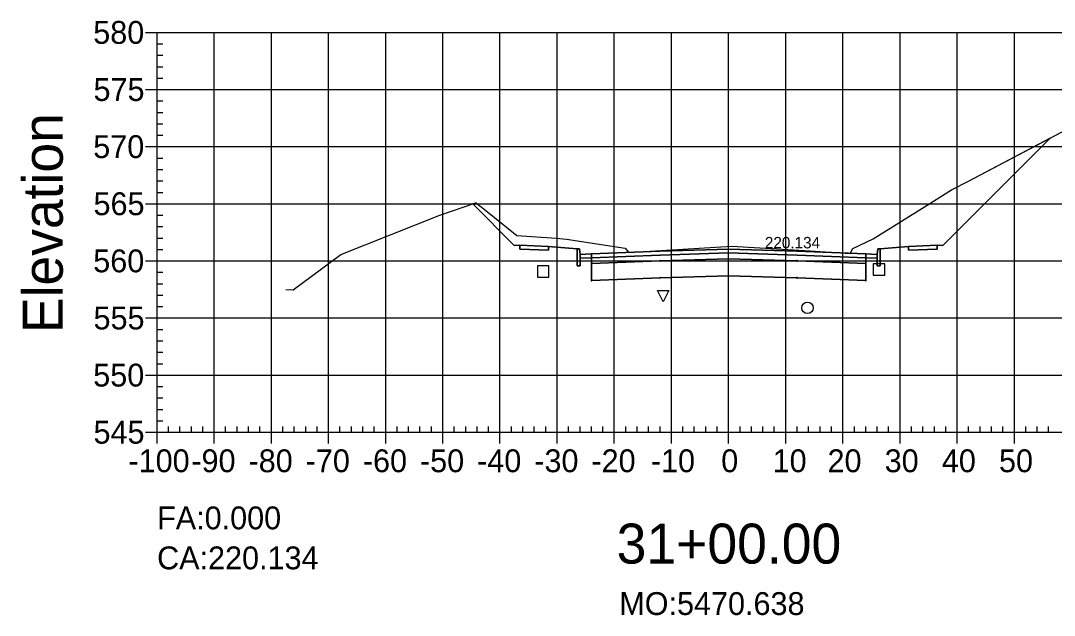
# Model space of a CAD drawing. Extents: x 704834 to 709892, y 372981 to 377533.
# Drawn here: x 706563 to 706743.9, y 373790.8 to 373894.9 of the extents above; entities that cross this region are included whole.
import ezdxf

# ---------------------------------------------------------------- set-up
doc = ezdxf.new("R2010")
doc.units = 0
for name, color, linetype in [('1', 7, 'Continuous'), ('10', 7, 'Continuous'), ('13', 7, 'Continuous'), ('14', 7, 'Continuous'), ('4', 7, 'Continuous'), ('57', 7, 'Continuous'), ('59', 7, 'Continuous'), ('60', 7, 'Continuous'), ('Default_Xsect', 7, 'Continuous'), ('Existing', 7, 'Continuous')]:
    doc.layers.add(name, color=color, linetype=linetype)

msp = doc.modelspace()

# ---------------------------------------------------------------- linework, layer by layer
for points in [[(706724.37, 373855.51), (706743.22, 373874.36)], [(706649.37, 373855.51), (706642.11, 373862.78)], [(706650.37, 373855.55), (706649.37, 373855.51)], [(706660.37, 373854.95), (706655.37, 373855.35)], [(706713.37, 373854.95), (706718.37, 373855.35)], [(706723.37, 373855.55), (706724.37, 373855.51)]]:
    msp.add_lwpolyline(points)
for points in [[(706655.37, 373855.35), (706650.37, 373855.55), (706650.37, 373854.88), (706655.37, 373854.68)], [(706718.37, 373854.68), (706723.37, 373854.88), (706723.37, 373855.55), (706718.37, 373855.35)], [(706660.87, 373853.95), (706660.79, 373854.95), (706660.37, 373854.95), (706660.37, 373851.95), (706660.87, 373851.95)], [(706662.87, 373854.03), (706660.87, 373853.95), (706660.87, 373853.28), (706662.87, 373853.36)], [(706686.87, 373854.2), (706698.87, 373853.84), (706710.87, 373853.36), (706710.87, 373854.03), (706698.87, 373854.51), (706686.87, 373854.87), (706674.87, 373854.51), (706662.87, 373854.03), (706662.87, 373853.36), (706674.87, 373853.84)], [(706686.87, 373853.2), (706698.87, 373852.84), (706710.87, 373852.36), (706710.87, 373853.36), (706698.87, 373853.84), (706686.87, 373854.2), (706674.87, 373853.84), (706662.87, 373853.36), (706662.87, 373852.36), (706674.87, 373852.84)], [(706686.82, 373854.15), (706686.92, 373854.15), (706686.92, 373854.25), (706686.82, 373854.25)], [(706710.87, 373853.36), (706712.87, 373853.28), (706712.87, 373853.95), (706710.87, 373854.03)], [(706712.87, 373851.95), (706713.37, 373851.95), (706713.37, 373854.95), (706712.96, 373854.95), (706712.87, 373853.95)], [(706662.82, 373852.31), (706662.92, 373852.31), (706662.92, 373852.41), (706662.82, 373852.41)], [(706686.87, 373850.2), (706698.87, 373849.84), (706710.87, 373849.36), (706710.87, 373852.36), (706698.87, 373852.84), (706686.87, 373853.2), (706674.87, 373852.84), (706662.87, 373852.36), (706662.87, 373849.36), (706674.87, 373849.84)], [(706674.82, 373852.79), (706674.92, 373852.79), (706674.92, 373852.89), (706674.82, 373852.89)], [(706686.82, 373853.15), (706686.92, 373853.15), (706686.92, 373853.25), (706686.82, 373853.25)], [(706698.82, 373852.79), (706698.92, 373852.79), (706698.92, 373852.89), (706698.82, 373852.89)], [(706710.82, 373852.31), (706710.92, 373852.31), (706710.92, 373852.41), (706710.82, 373852.41)], [(706674.82, 373849.79), (706674.92, 373849.79), (706674.92, 373849.89), (706674.82, 373849.89)], [(706686.82, 373850.15), (706686.92, 373850.15), (706686.92, 373850.25), (706686.82, 373850.25)], [(706698.82, 373849.79), (706698.92, 373849.79), (706698.92, 373849.89), (706698.82, 373849.89)], [(706662.82, 373849.31), (706662.92, 373849.31), (706662.92, 373849.41), (706662.82, 373849.41)], [(706710.82, 373849.31), (706710.92, 373849.31), (706710.92, 373849.41), (706710.82, 373849.41)]]:
    msp.add_lwpolyline(points, close=True)
at = {"layer": '1'}
for points in [[(706642.11, 373862.78), (706642.47, 373862.9), (706642.55, 373862.9), (706642.56, 373863.03), (706644.1, 373861.87), (706649.84, 373857.24), (706656.74, 373856.82), (706658.53, 373856.6), (706668.78, 373855.06), (706669.3, 373854.42), (706669.38, 373854.27), (706673.17, 373854.51), (706687.42, 373855.4), (706701.15, 373854.56), (706708.14, 373854.12), (706708.21, 373854.24), (706708.6, 373854.97), (706712.15, 373856.68), (706721.63, 373862.55), (706725.9, 373865.23), (706728.86, 373866.79), (706743.22, 373874.36), (706724.37, 373855.51), (706723.37, 373855.55), (706723.37, 373854.88), (706718.37, 373854.68), (706718.37, 373855.35), (706713.37, 373854.95), (706713.37, 373851.95), (706712.87, 373851.95), (706712.87, 373853.28), (706710.87, 373853.36), (706710.87, 373852.36), (706710.87, 373849.36), (706698.87, 373849.84), (706686.87, 373850.2), (706674.87, 373849.84), (706662.87, 373849.36), (706662.87, 373852.36), (706662.87, 373853.36), (706660.87, 373853.28), (706660.87, 373851.95), (706660.37, 373851.95), (706660.37, 373854.95), (706655.37, 373855.35), (706655.37, 373854.68), (706650.37, 373854.88), (706650.37, 373855.55), (706649.37, 373855.51)], [(706675.44, 373845.65), (706674.44, 373847.65), (706676.44, 373847.65)]]:
    msp.add_lwpolyline(points, close=True, dxfattribs=at)
at = {"layer": '10'}
msp.add_lwpolyline([(706653.43, 373849.96), (706655.43, 373849.96), (706655.43, 373851.96), (706653.43, 373851.96)], close=True, dxfattribs=at)
at = {"layer": '13'}
msp.add_circle((706700.67, 373844.59), 1, dxfattribs=at)
at = {"layer": '14'}
for points in [[(706743.22, 373874.36), (706743.22, 373874.41), (706743.22, 373874.36), (706743.17, 373874.36), (706743.22, 373874.36), (706743.22, 373874.31), (706743.22, 373874.36), (706743.27, 373874.36)], [(706642.11, 373862.78), (706642.11, 373862.83), (706642.11, 373862.78), (706642.06, 373862.78), (706642.11, 373862.78), (706642.11, 373862.73), (706642.11, 373862.78), (706642.16, 373862.78)], [(706662.87, 373854.03), (706662.87, 373854.08), (706662.87, 373854.03), (706662.82, 373854.03), (706662.87, 373854.03), (706662.87, 373853.98), (706662.87, 373854.03), (706662.92, 373854.03)], [(706674.87, 373854.51), (706674.87, 373854.56), (706674.87, 373854.51), (706674.82, 373854.51), (706674.87, 373854.51), (706674.87, 373854.46), (706674.87, 373854.51), (706674.92, 373854.51)], [(706686.87, 373854.87), (706686.87, 373854.92), (706686.87, 373854.87), (706686.82, 373854.87), (706686.87, 373854.87), (706686.87, 373854.82), (706686.87, 373854.87), (706686.92, 373854.87)], [(706698.87, 373854.51), (706698.87, 373854.56), (706698.87, 373854.51), (706698.82, 373854.51), (706698.87, 373854.51), (706698.87, 373854.46), (706698.87, 373854.51), (706698.92, 373854.51)], [(706710.87, 373854.03), (706710.87, 373854.08), (706710.87, 373854.03), (706710.82, 373854.03), (706710.87, 373854.03), (706710.87, 373853.98), (706710.87, 373854.03), (706710.92, 373854.03)]]:
    msp.add_lwpolyline(points, dxfattribs=at)
at = {"layer": '4'}
msp.add_lwpolyline([(706712.18, 373850.32), (706714.18, 373850.32), (706714.18, 373852.32), (706712.18, 373852.32)], close=True, dxfattribs=at)
at = {"layer": '57'}
for p, q in [((706584.87, 373892.82), (706586.87, 373892.82)), ((706586.87, 373892.82), (706786.87, 373892.82)), ((706586.87, 373822.82), (706586.87, 373892.82)), ((706586.87, 373822.82), (706586.87, 373892.82)), ((706596.87, 373822.82), (706596.87, 373892.82)), ((706606.87, 373822.82), (706606.87, 373892.82)), ((706616.87, 373822.82), (706616.87, 373892.82)), ((706626.87, 373822.82), (706626.87, 373892.82)), ((706636.87, 373822.82), (706636.87, 373892.82)), ((706646.87, 373822.82), (706646.87, 373892.82)), ((706656.87, 373822.82), (706656.87, 373892.82)), ((706666.87, 373822.82), (706666.87, 373892.82)), ((706676.87, 373822.82), (706676.87, 373892.82)), ((706686.87, 373822.82), (706686.87, 373892.82)), ((706696.87, 373822.82), (706696.87, 373892.82)), ((706706.87, 373822.82), (706706.87, 373892.82)), ((706716.87, 373822.82), (706716.87, 373892.82)), ((706726.87, 373822.82), (706726.87, 373892.82)), ((706736.87, 373822.82), (706736.87, 373892.82)), ((706586.87, 373890.82), (706587.87, 373890.82)), ((706586.87, 373888.82), (706587.87, 373888.82)), ((706586.87, 373886.82), (706587.87, 373886.82)), ((706586.87, 373884.82), (706587.87, 373884.82)), ((706584.87, 373882.82), (706586.87, 373882.82)), ((706586.87, 373882.82), (706786.87, 373882.82)), ((706586.87, 373880.82), (706587.87, 373880.82)), ((706586.87, 373878.82), (706587.87, 373878.82)), ((706586.87, 373876.82), (706587.87, 373876.82)), ((706586.87, 373874.82), (706587.87, 373874.82)), ((706584.87, 373872.82), (706586.87, 373872.82)), ((706586.87, 373872.82), (706786.87, 373872.82)), ((706586.87, 373870.82), (706587.87, 373870.82)), ((706586.87, 373868.82), (706587.87, 373868.82)), ((706586.87, 373866.82), (706587.87, 373866.82)), ((706586.87, 373864.82), (706587.87, 373864.82)), ((706584.87, 373862.82), (706586.87, 373862.82)), ((706586.87, 373862.82), (706786.87, 373862.82)), ((706586.87, 373860.82), (706587.87, 373860.82)), ((706586.87, 373858.82), (706587.87, 373858.82)), ((706586.87, 373856.82), (706587.87, 373856.82)), ((706586.87, 373854.82), (706587.87, 373854.82)), ((706584.87, 373852.82), (706586.87, 373852.82)), ((706586.87, 373852.82), (706786.87, 373852.82)), ((706586.87, 373850.82), (706587.87, 373850.82)), ((706586.87, 373848.82), (706587.87, 373848.82)), ((706586.87, 373846.82), (706587.87, 373846.82)), ((706586.87, 373844.82), (706587.87, 373844.82)), ((706584.87, 373842.82), (706586.87, 373842.82)), ((706586.87, 373842.82), (706786.87, 373842.82)), ((706586.87, 373840.82), (706587.87, 373840.82)), ((706586.87, 373838.82), (706587.87, 373838.82)), ((706586.87, 373836.82), (706587.87, 373836.82)), ((706586.87, 373834.82), (706587.87, 373834.82)), ((706584.87, 373832.82), (706586.87, 373832.82)), ((706586.87, 373832.82), (706786.87, 373832.82)), ((706586.87, 373830.82), (706587.87, 373830.82)), ((706586.87, 373828.82), (706587.87, 373828.82)), ((706586.87, 373826.82), (706587.87, 373826.82)), ((706586.87, 373824.82), (706587.87, 373824.82)), ((706584.87, 373822.82), (706586.87, 373822.82)), ((706586.87, 373822.82), (706786.87, 373822.82)), ((706586.87, 373822.82), (706786.87, 373822.82)), ((706586.87, 373820.82), (706586.87, 373822.82)), ((706588.87, 373822.82), (706588.87, 373823.82)), ((706590.87, 373822.82), (706590.87, 373823.82)), ((706592.87, 373822.82), (706592.87, 373823.82)), ((706594.87, 373822.82), (706594.87, 373823.82)), ((706596.87, 373820.82), (706596.87, 373822.82)), ((706598.87, 373822.82), (706598.87, 373823.82)), ((706600.87, 373822.82), (706600.87, 373823.82)), ((706602.87, 373822.82), (706602.87, 373823.82)), ((706604.87, 373822.82), (706604.87, 373823.82)), ((706606.87, 373820.82), (706606.87, 373822.82)), ((706608.87, 373822.82), (706608.87, 373823.82)), ((706610.87, 373822.82), (706610.87, 373823.82)), ((706612.87, 373822.82), (706612.87, 373823.82)), ((706614.87, 373822.82), (706614.87, 373823.82)), ((706616.87, 373820.82), (706616.87, 373822.82)), ((706618.87, 373822.82), (706618.87, 373823.82)), ((706620.87, 373822.82), (706620.87, 373823.82)), ((706622.87, 373822.82), (706622.87, 373823.82)), ((706624.87, 373822.82), (706624.87, 373823.82)), ((706626.87, 373820.82), (706626.87, 373822.82)), ((706628.87, 373822.82), (706628.87, 373823.82)), ((706630.87, 373822.82), (706630.87, 373823.82)), ((706632.87, 373822.82), (706632.87, 373823.82)), ((706634.87, 373822.82), (706634.87, 373823.82)), ((706636.87, 373820.82), (706636.87, 373822.82)), ((706638.87, 373822.82), (706638.87, 373823.82)), ((706640.87, 373822.82), (706640.87, 373823.82)), ((706642.87, 373822.82), (706642.87, 373823.82)), ((706644.87, 373822.82), (706644.87, 373823.82)), ((706646.87, 373820.82), (706646.87, 373822.82)), ((706648.87, 373822.82), (706648.87, 373823.82)), ((706650.87, 373822.82), (706650.87, 373823.82)), ((706652.87, 373822.82), (706652.87, 373823.82)), ((706654.87, 373822.82), (706654.87, 373823.82)), ((706656.87, 373820.82), (706656.87, 373822.82)), ((706658.87, 373822.82), (706658.87, 373823.82)), ((706660.87, 373822.82), (706660.87, 373823.82)), ((706662.87, 373822.82), (706662.87, 373823.82)), ((706664.87, 373822.82), (706664.87, 373823.82)), ((706666.87, 373820.82), (706666.87, 373822.82)), ((706668.87, 373822.82), (706668.87, 373823.82)), ((706670.87, 373822.82), (706670.87, 373823.82)), ((706672.87, 373822.82), (706672.87, 373823.82)), ((706674.87, 373822.82), (706674.87, 373823.82)), ((706676.87, 373820.82), (706676.87, 373822.82)), ((706678.87, 373822.82), (706678.87, 373823.82)), ((706680.87, 373822.82), (706680.87, 373823.82)), ((706682.87, 373822.82), (706682.87, 373823.82)), ((706684.87, 373822.82), (706684.87, 373823.82)), ((706686.87, 373820.82), (706686.87, 373822.82)), ((706688.87, 373822.82), (706688.87, 373823.82)), ((706690.87, 373822.82), (706690.87, 373823.82)), ((706692.87, 373822.82), (706692.87, 373823.82)), ((706694.87, 373822.82), (706694.87, 373823.82)), ((706696.87, 373820.82), (706696.87, 373822.82)), ((706698.87, 373822.82), (706698.87, 373823.82)), ((706700.87, 373822.82), (706700.87, 373823.82)), ((706702.87, 373822.82), (706702.87, 373823.82)), ((706704.87, 373822.82), (706704.87, 373823.82)), ((706706.87, 373820.82), (706706.87, 373822.82)), ((706708.87, 373822.82), (706708.87, 373823.82)), ((706710.87, 373822.82), (706710.87, 373823.82)), ((706712.87, 373822.82), (706712.87, 373823.82)), ((706714.87, 373822.82), (706714.87, 373823.82)), ((706716.87, 373820.82), (706716.87, 373822.82)), ((706718.87, 373822.82), (706718.87, 373823.82)), ((706720.87, 373822.82), (706720.87, 373823.82)), ((706722.87, 373822.82), (706722.87, 373823.82)), ((706724.87, 373822.82), (706724.87, 373823.82)), ((706726.87, 373820.82), (706726.87, 373822.82)), ((706728.87, 373822.82), (706728.87, 373823.82)), ((706730.87, 373822.82), (706730.87, 373823.82)), ((706732.87, 373822.82), (706732.87, 373823.82)), ((706734.87, 373822.82), (706734.87, 373823.82)), ((706736.87, 373820.82), (706736.87, 373822.82)), ((706738.87, 373822.82), (706738.87, 373823.82)), ((706740.87, 373822.82), (706740.87, 373823.82)), ((706742.87, 373822.82), (706742.87, 373823.82))]:
    msp.add_line(p, q, dxfattribs=at)
at = {"layer": 'Default_Xsect'}
msp.add_lwpolyline([(706642.11, 373862.78), (706649.37, 373855.51), (706650.37, 373855.55), (706655.37, 373855.35), (706660.37, 373854.95), (706660.79, 373854.95), (706660.87, 373853.95), (706662.87, 373854.03), (706674.87, 373854.51), (706686.87, 373854.87), (706698.87, 373854.51), (706710.87, 373854.03), (706712.87, 373853.95), (706712.96, 373854.95), (706713.37, 373854.95), (706718.37, 373855.35), (706723.37, 373855.55), (706724.37, 373855.51), (706743.22, 373874.36)], dxfattribs=at)
at = {"layer": 'Existing'}
msp.add_lwpolyline([(706609.38, 373847.83), (706610.7, 373847.75), (706619.04, 373853.93), (706636.33, 373860.85), (706642.47, 373862.9), (706642.55, 373862.9), (706642.56, 373863.03), (706644.1, 373861.87), (706649.84, 373857.24), (706656.74, 373856.82), (706658.53, 373856.6), (706668.78, 373855.06), (706669.3, 373854.42), (706669.38, 373854.27), (706673.17, 373854.51), (706687.42, 373855.4), (706701.15, 373854.56), (706708.14, 373854.12), (706708.21, 373854.24), (706708.6, 373854.97), (706712.15, 373856.68), (706721.63, 373862.55), (706725.9, 373865.23), (706728.86, 373866.79), (706748.34, 373877.06)], dxfattribs=at)

# ---------------------------------------------------------------- texts
msp.add_text('CA:220.134', height=4).set_placement((706586.87, 373798.82))
at = {"layer": '1'}
msp.add_text('31+00.00', height=7, dxfattribs=at).set_placement((706667.28, 373799.82))
at = {"layer": '14'}
for p in [(706650.34, 373855.5), (706723.34, 373855.5), (706650.34, 373854.83), (706655.34, 373854.63), (706718.34, 373854.63), (706723.34, 373854.83)]:
    msp.add_text('+', height=0.1, dxfattribs=at).set_placement(p)
at = {"layer": '57'}
for s, p in [('580', (706575.7, 373890.82)), ('575', (706575.75, 373880.82)), ('570', (706575.7, 373870.82)), ('565', (706575.75, 373860.82)), ('560', (706575.7, 373850.82)), ('555', (706575.75, 373840.82)), ('550', (706575.7, 373830.82)), ('545', (706575.75, 373820.82)), ('-100', (706581.86, 373815.82)), ('-90', (706592.87, 373815.82)), ('-80', (706602.87, 373815.82)), ('-70', (706612.87, 373815.82)), ('-60', (706622.87, 373815.82)), ('-50', (706632.87, 373815.82)), ('-40', (706642.87, 373815.82)), ('-30', (706652.87, 373815.82)), ('-20', (706662.87, 373815.82)), ('-10', (706673.26, 373815.82)), ('0', (706685.58, 373815.82)), ('10', (706694.57, 373815.82)), ('20', (706704.18, 373815.82)), ('30', (706714.18, 373815.82)), ('40', (706724.18, 373815.82)), ('50', (706734.18, 373815.82))]:
    msp.add_text(s, height=4, dxfattribs=at).set_placement(p)
at = {"layer": '59'}
for s, height, p in [('220.134', 2, (706693.21, 373855.01)), ('FA:0.000', 4, (706586.87, 373805.82)), ('MO:5470.638', 4, (706667.74, 373790.82))]:
    msp.add_text(s, height=height, dxfattribs=at).set_placement(p)
at = {"layer": '60'}
msp.add_text('Elevation', height=7, rotation=90, dxfattribs=at).set_placement((706570.37, 373840.18))

doc.saveas('drawing.dxf')
